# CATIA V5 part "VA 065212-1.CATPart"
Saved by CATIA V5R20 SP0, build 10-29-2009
Part number: VA 065212-1
Revision: ANY
Definition: UNKNOWN
Nomenclature: VA 065212-1
Source: Unknown
Bounding box of the stored display mesh (mm): x -2.603 to 2.603, y 0 to 10.252, z -2.476 to 2.476
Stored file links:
  C:\Users\Utente\Desktop\IO LAVORO\3D X SITO CF\CUMSA\3D files VA\VA 065212\VA 065212-1.CATPart
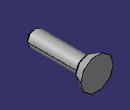
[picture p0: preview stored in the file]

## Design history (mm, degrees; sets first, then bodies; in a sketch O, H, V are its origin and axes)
Body1 "Cortar-Extruir1" (main body)
  Solid1: solid without history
